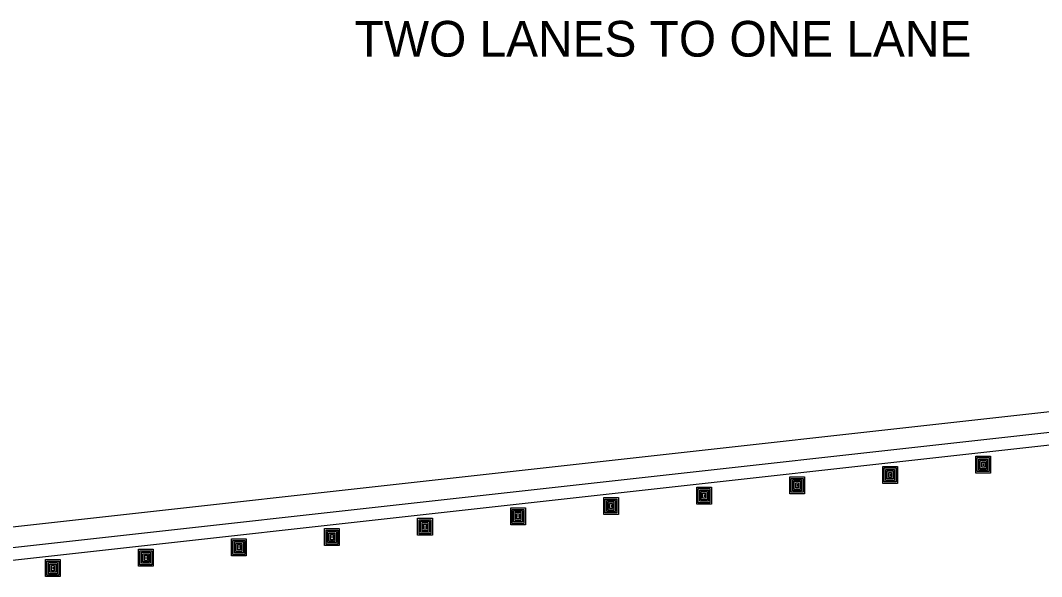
# Model space of a CAD drawing. Extents: x 639362 to 641108, y 298458 to 299646.
# Drawn here: x 639604.4 to 639727.1, y 298620.2 to 298687.1 of the extents above; entities that cross this region are included whole.
import ezdxf

# ---------------------------------------------------------------- set-up
doc = ezdxf.new("R2010")
doc.units = 0
doc.layers.add('2', color=7, linetype='Continuous')

msp = doc.modelspace()

# ---------------------------------------------------------------- linework, layer by layer
at = {"layer": '2'}
for p, q in [((639585.9, 298624.2), (639797.99, 298647.81)), ((639585.9, 298621.7), (639797.99, 298645.31)), ((639585.9, 298620.2), (639797.99, 298643.81)), ((639719.22, 298634.65), (639720.99, 298634.65)), ((639719.22, 298632.61), (639719.22, 298634.65)), ((639719.39, 298634.47), (639720.81, 298634.47)), ((639719.39, 298632.79), (639719.39, 298634.47)), ((639719.57, 298634.3), (639720.64, 298634.3)), ((639719.57, 298632.97), (639719.57, 298634.3)), ((639719.75, 298633.14), (639719.75, 298634.12)), ((639719.75, 298634.12), (639720.46, 298634.12)), ((639719.93, 298633.94), (639720.28, 298633.94)), ((639719.93, 298633.32), (639719.93, 298633.94)), ((639720.28, 298633.94), (639720.28, 298633.32)), ((639720.46, 298634.12), (639720.46, 298633.14)), ((639720.64, 298634.3), (639720.64, 298632.97)), ((639720.81, 298634.47), (639720.81, 298632.79)), ((639720.99, 298634.65), (639720.99, 298632.61)), ((639708.03, 298633.41), (639709.81, 298633.41)), ((639708.03, 298631.37), (639708.03, 298633.41)), ((639708.21, 298633.23), (639709.63, 298633.23)), ((639708.21, 298631.54), (639708.21, 298633.23)), ((639708.39, 298633.05), (639709.45, 298633.05)), ((639708.39, 298631.72), (639708.39, 298633.05)), ((639708.56, 298631.9), (639708.56, 298632.87)), ((639708.56, 298632.87), (639709.27, 298632.87)), ((639708.74, 298632.7), (639709.1, 298632.7)), ((639708.74, 298632.08), (639708.74, 298632.7)), ((639709.1, 298632.7), (639709.1, 298632.08)), ((639709.27, 298632.87), (639709.27, 298631.9)), ((639709.45, 298633.05), (639709.45, 298631.72)), ((639709.63, 298633.23), (639709.63, 298631.54)), ((639709.81, 298633.41), (639709.81, 298631.37)), ((639720.81, 298632.79), (639719.39, 298632.79)), ((639720.64, 298632.97), (639719.57, 298632.97)), ((639720.46, 298633.14), (639719.75, 298633.14)), ((639720.28, 298633.32), (639719.93, 298633.32)), ((639720.1, 298633.77), (639720.1, 298633.5)), ((639696.85, 298632.16), (639698.62, 298632.16)), ((639696.85, 298630.12), (639696.85, 298632.16)), ((639697.03, 298631.98), (639698.45, 298631.98)), ((639697.03, 298630.3), (639697.03, 298631.98)), ((639697.2, 298631.8), (639698.27, 298631.8)), ((639697.2, 298630.48), (639697.2, 298631.8)), ((639697.38, 298630.65), (639697.38, 298631.63)), ((639697.38, 298631.63), (639698.09, 298631.63)), ((639697.56, 298631.45), (639697.91, 298631.45)), ((639697.56, 298630.83), (639697.56, 298631.45)), ((639697.91, 298631.45), (639697.91, 298630.83)), ((639698.09, 298631.63), (639698.09, 298630.65)), ((639698.27, 298631.8), (639698.27, 298630.48)), ((639698.45, 298631.98), (639698.45, 298630.3)), ((639698.62, 298632.16), (639698.62, 298630.12)), ((639709.63, 298631.54), (639708.21, 298631.54)), ((639709.45, 298631.72), (639708.39, 298631.72)), ((639709.27, 298631.9), (639708.56, 298631.9)), ((639709.1, 298632.08), (639708.74, 298632.08)), ((639708.92, 298632.52), (639708.92, 298632.25)), ((639720.99, 298632.61), (639719.22, 298632.61)), ((639685.66, 298630.91), (639687.44, 298630.91)), ((639685.66, 298628.88), (639685.66, 298630.91)), ((639685.84, 298630.74), (639687.26, 298630.74)), ((639685.84, 298629.05), (639685.84, 298630.74)), ((639686.02, 298630.56), (639687.08, 298630.56)), ((639686.02, 298629.23), (639686.02, 298630.56)), ((639686.2, 298629.41), (639686.2, 298630.38)), ((639686.2, 298630.38), (639686.91, 298630.38)), ((639686.38, 298630.21), (639686.73, 298630.21)), ((639686.38, 298629.59), (639686.38, 298630.21)), ((639686.73, 298630.21), (639686.73, 298629.59)), ((639686.91, 298630.38), (639686.91, 298629.41)), ((639687.08, 298630.56), (639687.08, 298629.23)), ((639687.26, 298630.74), (639687.26, 298629.05)), ((639687.44, 298630.91), (639687.44, 298628.88)), ((639698.45, 298630.3), (639697.03, 298630.3)), ((639698.27, 298630.48), (639697.2, 298630.48)), ((639698.09, 298630.65), (639697.38, 298630.65)), ((639697.91, 298630.83), (639697.56, 298630.83)), ((639697.73, 298631.28), (639697.73, 298631.01)), ((639709.81, 298631.37), (639708.03, 298631.37)), ((639674.48, 298629.67), (639676.26, 298629.67)), ((639674.48, 298627.63), (639674.48, 298629.67)), ((639674.66, 298629.49), (639676.08, 298629.49)), ((639674.66, 298627.81), (639674.66, 298629.49)), ((639674.84, 298629.31), (639675.9, 298629.31)), ((639674.84, 298627.99), (639674.84, 298629.31)), ((639675.01, 298628.16), (639675.01, 298629.14)), ((639675.01, 298629.14), (639675.72, 298629.14)), ((639675.19, 298628.96), (639675.55, 298628.96)), ((639675.19, 298628.34), (639675.19, 298628.96)), ((639675.55, 298628.96), (639675.55, 298628.34)), ((639675.72, 298629.14), (639675.72, 298628.16)), ((639675.9, 298629.31), (639675.9, 298627.99)), ((639676.08, 298629.49), (639676.08, 298627.81)), ((639676.26, 298629.67), (639676.26, 298627.63)), ((639687.26, 298629.05), (639685.84, 298629.05)), ((639687.08, 298629.23), (639686.02, 298629.23)), ((639686.91, 298629.41), (639686.2, 298629.41)), ((639686.73, 298629.59), (639686.38, 298629.59)), ((639686.55, 298630.03), (639686.55, 298629.76)), ((639698.62, 298630.12), (639696.85, 298630.12)), ((639663.3, 298628.42), (639665.07, 298628.42)), ((639663.3, 298626.39), (639663.3, 298628.42)), ((639663.47, 298628.25), (639664.89, 298628.25)), ((639663.47, 298626.56), (639663.47, 298628.25)), ((639663.65, 298628.07), (639664.72, 298628.07)), ((639663.65, 298626.74), (639663.65, 298628.07)), ((639663.83, 298626.92), (639663.83, 298627.89)), ((639663.83, 298627.89), (639664.54, 298627.89)), ((639664.01, 298627.72), (639664.36, 298627.72)), ((639664.01, 298627.09), (639664.01, 298627.72)), ((639664.36, 298627.72), (639664.36, 298627.09)), ((639664.54, 298627.89), (639664.54, 298626.92)), ((639664.72, 298628.07), (639664.72, 298626.74)), ((639664.89, 298628.25), (639664.89, 298626.56)), ((639665.07, 298628.42), (639665.07, 298626.39)), ((639676.08, 298627.81), (639674.66, 298627.81)), ((639675.9, 298627.99), (639674.84, 298627.99)), ((639675.72, 298628.16), (639675.01, 298628.16)), ((639675.55, 298628.34), (639675.19, 298628.34)), ((639675.37, 298628.79), (639675.37, 298628.52)), ((639687.44, 298628.88), (639685.66, 298628.88)), ((639652.11, 298627.18), (639653.89, 298627.18)), ((639652.11, 298625.14), (639652.11, 298627.18)), ((639652.29, 298627), (639653.71, 298627)), ((639652.29, 298625.32), (639652.29, 298627)), ((639652.47, 298626.82), (639653.53, 298626.82)), ((639652.47, 298625.5), (639652.47, 298626.82)), ((639652.65, 298625.67), (639652.65, 298626.65)), ((639652.65, 298626.65), (639653.36, 298626.65)), ((639653.36, 298626.65), (639653.36, 298625.67)), ((639653.53, 298626.82), (639653.53, 298625.5)), ((639653.71, 298627), (639653.71, 298625.32)), ((639653.89, 298627.18), (639653.89, 298625.14)), ((639664.89, 298626.56), (639663.47, 298626.56)), ((639664.72, 298626.74), (639663.65, 298626.74)), ((639664.54, 298626.92), (639663.83, 298626.92)), ((639664.36, 298627.09), (639664.01, 298627.09)), ((639664.18, 298627.54), (639664.18, 298627.27)), ((639676.26, 298627.63), (639674.48, 298627.63)), ((639640.93, 298625.93), (639642.7, 298625.93)), ((639640.93, 298623.89), (639640.93, 298625.93)), ((639641.11, 298625.76), (639642.53, 298625.76)), ((639641.11, 298624.07), (639641.11, 298625.76)), ((639641.29, 298625.58), (639642.35, 298625.58)), ((639641.29, 298624.25), (639641.29, 298625.58)), ((639641.46, 298624.43), (639641.46, 298625.4)), ((639641.46, 298625.4), (639642.17, 298625.4)), ((639642.17, 298625.4), (639642.17, 298624.43)), ((639642.35, 298625.58), (639642.35, 298624.25)), ((639642.53, 298625.76), (639642.53, 298624.07)), ((639642.7, 298625.93), (639642.7, 298623.89)), ((639653.71, 298625.32), (639652.29, 298625.32)), ((639653.53, 298625.5), (639652.47, 298625.5)), ((639653.36, 298625.67), (639652.65, 298625.67)), ((639652.82, 298626.47), (639653.18, 298626.47)), ((639652.82, 298625.85), (639652.82, 298626.47)), ((639653.18, 298625.85), (639652.82, 298625.85)), ((639653, 298626.29), (639653, 298626.03)), ((639653.18, 298626.47), (639653.18, 298625.85)), ((639665.07, 298626.39), (639663.3, 298626.39)), ((639629.75, 298624.69), (639631.52, 298624.69)), ((639629.75, 298622.65), (639629.75, 298624.69)), ((639629.92, 298624.51), (639631.34, 298624.51)), ((639629.92, 298622.83), (639629.92, 298624.51)), ((639630.1, 298624.33), (639631.17, 298624.33)), ((639630.1, 298623.01), (639630.1, 298624.33)), ((639630.28, 298623.18), (639630.28, 298624.16)), ((639630.28, 298624.16), (639630.99, 298624.16)), ((639630.99, 298624.16), (639630.99, 298623.18)), ((639631.17, 298624.33), (639631.17, 298623.01)), ((639631.34, 298624.51), (639631.34, 298622.83)), ((639631.52, 298624.69), (639631.52, 298622.65)), ((639642.53, 298624.07), (639641.11, 298624.07)), ((639642.35, 298624.25), (639641.29, 298624.25)), ((639642.17, 298624.43), (639641.46, 298624.43)), ((639641.64, 298625.23), (639641.99, 298625.23)), ((639641.64, 298624.6), (639641.64, 298625.23)), ((639641.99, 298624.6), (639641.64, 298624.6)), ((639641.81, 298625.05), (639641.81, 298624.78)), ((639641.99, 298625.23), (639641.99, 298624.6)), ((639653.89, 298625.14), (639652.11, 298625.14)), ((639618.56, 298623.44), (639620.34, 298623.44)), ((639618.56, 298621.4), (639618.56, 298623.44)), ((639618.74, 298623.27), (639620.16, 298623.27)), ((639618.74, 298621.58), (639618.74, 298623.27)), ((639618.92, 298623.09), (639619.98, 298623.09)), ((639618.92, 298621.76), (639618.92, 298623.09)), ((639619.09, 298621.94), (639619.09, 298622.91)), ((639619.09, 298622.91), (639619.8, 298622.91)), ((639619.8, 298622.91), (639619.8, 298621.94)), ((639619.98, 298623.09), (639619.98, 298621.76)), ((639620.16, 298623.27), (639620.16, 298621.58)), ((639620.34, 298623.44), (639620.34, 298621.4)), ((639631.34, 298622.83), (639629.92, 298622.83)), ((639631.17, 298623.01), (639630.1, 298623.01)), ((639630.99, 298623.18), (639630.28, 298623.18)), ((639630.46, 298623.98), (639630.81, 298623.98)), ((639630.46, 298623.36), (639630.46, 298623.98)), ((639630.81, 298623.36), (639630.46, 298623.36)), ((639630.63, 298623.8), (639630.63, 298623.54)), ((639630.81, 298623.98), (639630.81, 298623.36)), ((639642.7, 298623.89), (639640.93, 298623.89)), ((639607.38, 298622.2), (639609.15, 298622.2)), ((639607.38, 298620.16), (639607.38, 298622.2)), ((639607.56, 298622.02), (639608.98, 298622.02)), ((639607.56, 298620.34), (639607.56, 298622.02)), ((639607.73, 298621.84), (639608.8, 298621.84)), ((639607.73, 298620.51), (639607.73, 298621.84)), ((639607.91, 298620.69), (639607.91, 298621.67)), ((639607.91, 298621.67), (639608.62, 298621.67)), ((639608.62, 298621.67), (639608.62, 298620.69)), ((639608.8, 298621.84), (639608.8, 298620.51)), ((639608.98, 298622.02), (639608.98, 298620.34)), ((639609.15, 298622.2), (639609.15, 298620.16)), ((639620.16, 298621.58), (639618.74, 298621.58)), ((639619.98, 298621.76), (639618.92, 298621.76)), ((639619.8, 298621.94), (639619.09, 298621.94)), ((639619.27, 298622.74), (639619.63, 298622.74)), ((639619.27, 298622.11), (639619.27, 298622.74)), ((639619.63, 298622.11), (639619.27, 298622.11)), ((639619.45, 298622.56), (639619.45, 298622.29)), ((639619.63, 298622.74), (639619.63, 298622.11)), ((639631.52, 298622.65), (639629.75, 298622.65)), ((639608.8, 298620.51), (639607.73, 298620.51)), ((639608.62, 298620.69), (639607.91, 298620.69)), ((639608.09, 298621.49), (639608.44, 298621.49)), ((639608.09, 298620.87), (639608.09, 298621.49)), ((639608.44, 298620.87), (639608.09, 298620.87)), ((639608.26, 298621.31), (639608.26, 298621.05)), ((639608.44, 298621.49), (639608.44, 298620.87)), ((639620.34, 298621.4), (639618.56, 298621.4)), ((639609.15, 298620.16), (639607.38, 298620.16)), ((639608.98, 298620.34), (639607.56, 298620.34))]:
    msp.add_line(p, q, dxfattribs=at)

# ---------------------------------------------------------------- texts
msp.add_text('TWO LANES TO ONE LANE', height=4.3, dxfattribs=at).set_placement((639644.55, 298682.71))

doc.saveas('drawing.dxf')
